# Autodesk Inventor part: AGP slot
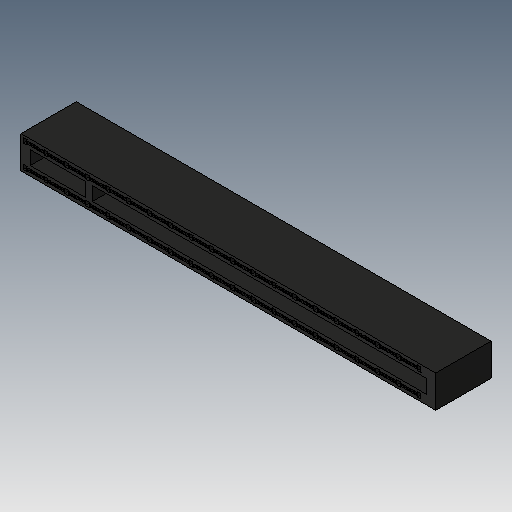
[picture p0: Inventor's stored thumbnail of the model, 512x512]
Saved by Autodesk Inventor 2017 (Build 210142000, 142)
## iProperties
Created: 2005-12
Part Number: AGP slot
Material: Generic
Document SubType Name: Modeling
Designer: DanielSeverino
Density: 1 g/cm^3
Appearance: Default
Author: DanielSeverino
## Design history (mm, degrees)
feature "Solid1"
body "Solid2"
